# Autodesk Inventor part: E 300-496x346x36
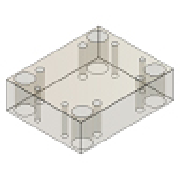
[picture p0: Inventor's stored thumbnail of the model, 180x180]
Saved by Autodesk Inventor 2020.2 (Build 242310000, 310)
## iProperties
IsCustomPart: 1
Manager: www.cadconsulting.pl
Company: Fabian Stasiak CAD Consulting
Created: 2014-02
Part Number: E 300-496x346x36
Material: S 55 C
Description: Support Plate
Document SubType Name: Modeling
Designer: F.Stasiak
Standard Revision: 1
Manufacturer: DME
Language: pl-PL
Size Designation: 496x346x36
Categories: <MemberInstance><Categories><Category DisplayName="Forma wtryskowa" InternalName="349578f2-f4d4-4954-8c09-8e99297a61c0" Mnemonic="MOLD"><Category DisplayName="P
Density: 7.85 g/cm^3
Appearance: Polycarbonate - Smoked
Catalog Web Link: www.expertbooks.pl
Author: F.Stasiak
Subject: Zbiór ćwiczeń. Autodesk Inventor 2020. Kurs Professional
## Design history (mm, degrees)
sketch "Sketch1"
  geometry: L1 (-173, 248)-(173, 248); L2 (173, 248)-(173, -248); L3 (173, -248)-(-173, -248); L4 (-173, -248)-(-173, 248); 6 further points
  constraints: 8 end point, 2 midpoint, 2 parallel, 1 horizontal, 1 horizontal alignment, 1 perpendicular, 1 vertical alignment
  dimensions: "d126" = 346 distance between parallel lines of L2 L4 (= W_); "d127" = 496 distance between parallel lines of L3 L1 (= L); "d128" = 95 horizontal distance of point (0, 0) point (-95, 233) (= 0.5 x RP_W); "d129" = 233 vertical distance of point (0, 0) point (-95, 233) (= 0.5 x RP_L); "d130" = 137 horizontal distance of point (0, 0) point (-137, 165) (= 0.5 x S1_W); "d131" = 165 vertical distance of point (0, 0) point (-137, 165) (= 0.5 x S1_L); "d132" = 208 vertical distance of point (0, 0) point (-137, 208) (= 0.5 x LS_L); "d133" = 137 horizontal distance of point (0, 0) point (-137, 208) (= 0.5 x LS_W)
extrude "Extrusion1" new body sketch "Sketch1" distance "d20" = 36 (= H_); taper "d30" = 0 deg
hole "Hole1" sketch "Sketch1" diameter "d134" = 42 (= LS_dt); stored, may be unused: countersink angle "d138" = 90 deg, drill point angle "d140" = 0 deg; dims "d135" = 6, "d136" = 4, "d137" = 2, "d139" = 36 (= H_)
pattern_linear "Rectangular Pattern1" dims "d163" = 416 (computed from LS_L, Nl), "d166" = 274 (computed from LS_W, Nw)
hole "Hole2" sketch "Sketch1" diameter "d141" = 18 (= S1_dt); stored, may be unused: countersink angle "d145" = 90 deg, drill point angle "d147" = 0 deg; dims "d142" = 6, "d143" = 4, "d144" = 2, "d146" = 36 (= H_)
pattern_linear "Rectangular Pattern2" dims "d157" = 330 (computed from S1_L, Ns), "d160" = 274 (computed from S1_W, Nw)
hole "Hole3" sketch "Sketch1" diameter "d148" = 14 (= RP_dt); stored, may be unused: countersink angle "d152" = 90 deg, drill point angle "d154" = 0 deg; dims "d149" = 6, "d150" = 4, "d151" = 2, "d153" = 36 (= H_)
pattern_linear "Rectangular Pattern3" dims "d169" = 466 (computed from RP_L, Nl), "d172" = 190 (computed from RP_W, Nw)
chamfer "Chamfer1" distance "d173" = 0.5; stored, may be unused: second distance "d174" = 2, angle "d175" = 45 deg
sketch "Szkic2"
  geometry: 1 further point
hole "Otwór12" sketch "Szkic2" at (0, 0) diameter "d176" = 4.5; stored, may be unused: countersink angle "d180" = 90 deg, drill point angle "d182" = 0 deg; dims "d177" = 6, "d178" = 4, "d179" = 2, "d181" = 8
sketch "Szkic3"
  geometry: 4 further points
hole "Otwór13" sketch "Szkic3" at (-54, 134), (-24, -134), (24, 134), (54, -134) diameter "d183" = 5; stored, may be unused: countersink angle "d187" = 90 deg, drill point angle "d189" = 0 deg; dims "d184" = 6, "d185" = 4, "d186" = 2, "d188" = 8
sketch "Szkic4"
  geometry: 4 further points
hole "Otwór14" sketch "Szkic4" at (-24, 134), (-54, -134), (54, 134), (24, -134) diameter "d190" = 5; stored, may be unused: countersink angle "d194" = 90 deg, drill point angle "d196" = 0 deg; dims "d191" = 6, "d192" = 4, "d193" = 2, "d195" = 8
sketch "Szkic5"
  geometry: 4 further points
hole "Otwór15" sketch "Szkic5" at (-54, 103.5), (-24, -103.5), (24, 103.5), (54, -103.5) diameter "d197" = 5; stored, may be unused: countersink angle "d201" = 90 deg, drill point angle "d203" = 0 deg; dims "d198" = 6, "d199" = 4, "d200" = 2, "d202" = 8
sketch "Szkic6"
  geometry: 4 further points
hole "Otwór16" sketch "Szkic6" at (-24, 103.5), (-54, -103.5), (54, 103.5), (24, -103.5) diameter "d204" = 5; stored, may be unused: countersink angle "d208" = 90 deg, drill point angle "d210" = 0 deg; dims "d205" = 6, "d206" = 4, "d207" = 2, "d209" = 8
sketch "Szkic7"
  geometry: 4 further points
hole "Otwór17" sketch "Szkic7" at (-47, 71.2), (-31, -71.2), (31, 71.2), (47, -71.2) diameter "d211" = 5; stored, may be unused: countersink angle "d215" = 90 deg, drill point angle "d217" = 0 deg; dims "d212" = 6, "d213" = 4, "d214" = 2, "d216" = 8
sketch "Szkic8"
  geometry: 4 further points
hole "Otwór18" sketch "Szkic8" at (-31, 71.2), (-47, -71.2), (47, 71.2), (31, -71.2) diameter "d218" = 5; stored, may be unused: countersink angle "d222" = 90 deg, drill point angle "d224" = 0 deg; dims "d219" = 6, "d220" = 4, "d221" = 2, "d223" = 8
sketch "Szkic9"
  geometry: 4 further points
hole "Otwór19" sketch "Szkic9" at (-48.5, 54), (-29.5, -54), (29.5, 54), (48.5, -54) diameter "d225" = 5; stored, may be unused: countersink angle "d229" = 90 deg, drill point angle "d231" = 0 deg; dims "d226" = 6, "d227" = 4, "d228" = 2, "d230" = 8
sketch "Szkic10"
  geometry: 4 further points
hole "Otwór20" sketch "Szkic10" at (-29.5, 54), (-48.5, -54), (48.5, 54), (29.5, -54) diameter "d232" = 5; stored, may be unused: countersink angle "d236" = 90 deg, drill point angle "d238" = 0 deg; dims "d233" = 6, "d234" = 4, "d235" = 2, "d237" = 8
sketch "Szkic11"
  geometry: 4 further points
hole "Otwór21" sketch "Szkic11" at (-57, 29), (-21, -29), (21, 29), (57, -29) diameter "d239" = 5; stored, may be unused: countersink angle "d243" = 90 deg, drill point angle "d245" = 0 deg; dims "d240" = 6, "d241" = 4, "d242" = 2, "d244" = 8
sketch "Szkic12"
  geometry: 4 further points
hole "Otwór22" sketch "Szkic12" at (-39, 35), (-39, -35), (39, 35), (39, -35) diameter "d246" = 5; stored, may be unused: countersink angle "d250" = 90 deg, drill point angle "d252" = 0 deg; dims "d247" = 6, "d248" = 4, "d249" = 2, "d251" = 8
sketch "Szkic13"
  geometry: 4 further points
hole "Otwór23" sketch "Szkic13" at (-21, 29), (-57, -29), (57, 29), (21, -29) diameter "d253" = 5; stored, may be unused: countersink angle "d257" = 90 deg, drill point angle "d259" = 0 deg; dims "d254" = 6, "d255" = 4, "d256" = 2, "d258" = 8
body "Solid1"
other parameters: "L" = 496 [user parameter; used in 1 equation term], "W_" = 346 [user parameter; used in 1 equation term], "H_" = 36 [user parameter; used in 4 equation terms], "LS_W" = 274 [user parameter; used in 2 equation terms], "LS_dt" = 42 [user parameter; used in 1 equation term], "S1_W" = 274 [user parameter; used in 2 equation terms], "RP_L" = 466 [user parameter; used in 2 equation terms], "RP_dt" = 14 [user parameter; used in 1 equation term], "LS_L" = 416 [user parameter; used in 2 equation terms], "S1_dt" = 18 [user parameter; used in 1 equation term]
